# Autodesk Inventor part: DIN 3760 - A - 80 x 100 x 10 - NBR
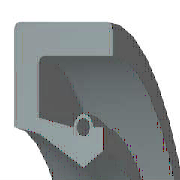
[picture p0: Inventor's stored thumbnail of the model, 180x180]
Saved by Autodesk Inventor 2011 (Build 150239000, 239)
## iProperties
IsCustomPart: 0
Created: 2010-02
Part Number: DIN 3760 - A - 80 x 100 x 10 - NBR
Material: Rubber
Description: Shaft Seal Ring
Document SubType Name: Modeling
Standard: DIN 3760
Designer: 129877
Standards Organization: DIN
Language: en-US
Size Designation: A - 80 x 100 x 10 - NBR
Categories: <MemberInstance><Categories><Category DisplayName="Shaft Parts" InternalName="7f7aeb1f-a693-4053-b835-cee3144e0d98" Mnemonic="SHFT"><Category DisplayName="Seali
Density: 0.93 g/cm^3
Mass: 12.9895 g
Surface Area: 142.913 cm^2
Volume: 13.9672 cm^3
Author: 129877
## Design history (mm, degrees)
revolve "Body" stored, may be unused: angle "d17" = 90 deg
revolve "Spring1" stored, may be unused: angle "d18" = 90 deg
body "Solid1"
sketch "Sketch1"
  geometry: L1 (0, 50)-(10, 50); L2 (10, 50)-(10, 48); L3 (10, 48)-(2.5, 48); L4 (0, 50)-(0, 43); L5 (0, 43)-(2.5, 42.5); L6 (2.5, 42.5)-(7, 40); L7 (7, 40)-(0, 40); L8 (9, 41.25)-(9, 43); L9 (0, 0)-(9.586, 0) reference; L10 (7, 40)-(9, 41.25); L11 (0, 18)-(0, -3) reference; L12 (-1.917, 0)-(11.503, 0) reference; L13 (6, 43)-(2.5, 43.7); L14 (2.5, 43.7)-(2.5, 48); L15 (9, 43)-(8, 43); C1 r 0.65 at (7, 43); A1 r 1 centre (7, 43) between (8, 43) and (6, 43)
  constraints: 26 end point, 5 horizontal alignment, 4 perpendicular, 2 centre point, 2 collinear, 2 horizontal, 2 parallel, 2 point on circle, 2 point on line, 2 vertical alignment, 1 coincident
  dimensions: "d0" = 100 diameter of L1 L9 (= SD2); "d1" = 82.5 diameter of L8.start L9 (= ABDM); "d2" = 2 distance of L1.end L2.end (computed from SD); "d3" = 1.3 diameter of C1 (= SPDI); "d4" = 2 diameter of A1 (= SPDA); "d5" = 80 diameter of L6.end L9 (= NND); "d6" = 85 diameter of L5.end L9 (= TKDM); "d7" = 86 diameter of L4.end L9 (= HLDM); "d8" = 7 distance from line of C1.centre L4 (= SPDST); "d9" = 9 distance between parallel lines of L8 L4 (= SDI); "d10" = 10 distance between parallel lines of L2 L4 (= SWDT); "d12" = 2.5 distance between parallel lines of L14 L4 (= SD)
fillet "Fillet1" dims "d11" = 0.5 (= RR)
other parameters: "SD2" = 100 [user parameter; used in 1 equation term], "SWDT" = 10 [user parameter; used in 1 equation term], "RR" = 0.5 [user parameter; used in 1 equation term], "SD" = 2.5 [user parameter; used in 2 equation terms], "NND" = 80 [user parameter; used in 1 equation term], "SPDA" = 2 [user parameter; used in 1 equation term], "SPDI" = 1.3 [user parameter; used in 1 equation term], "TKDM" = 85 [user parameter; used in 1 equation term], "HLDM" = 86 [user parameter; used in 1 equation term], "ABDM" = 82.5 [user parameter; used in 1 equation term], "SDI" = 9 [user parameter; used in 1 equation term], "SPDST" = 7 [user parameter; used in 1 equation term], "d13" = 0, "d14" = 0, "d15" = 0, "LAB" = 0.5 [user parameter]
